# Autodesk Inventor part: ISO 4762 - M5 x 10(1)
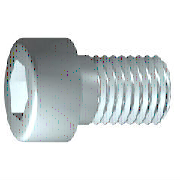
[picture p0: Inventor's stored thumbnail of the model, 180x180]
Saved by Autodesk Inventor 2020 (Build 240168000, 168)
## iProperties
IsCustomPart: 0
Created: 2019-01
Part Number: ISO 4762 - M5 x 10(1)
Material: Nerezová ocel 440C
Description: Šroub s válcovou hlavou s vnitřním šestihranem
Document SubType Name: Modeling
Standard: ISO 4762
Designer: doma
Standard Revision: Fourth edition 2004-03-01
Standards Organization: ISO
Language: cs-CZ
Size Designation: M5 x 10
Categories: <MemberInstance><Categories><Category DisplayName="Spojovací materiál" InternalName="e4da775c-781d-43d5-af7c-5136215cf5a6" Mnemonic="FSTN"><Category DisplayName
Density: 7.75 g/cm^3
Appearance: Pololeštěná
Mass: 3.37173 g
Surface Area: 4.31157 cm^2
Volume: 0.435062 cm^3
Author: doma
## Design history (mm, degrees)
sketch "Náčrt1"
  geometry: L1 (-1.167, 0)-(10, 0); L2 (10, 0)-(10, 2.5); L3 (10, 2.5)-(2, 2.5); L4 (2, 2.5)-(1.509, 2.5); L5 (1.509, 2.5)-(0, 2.5); L6 (0, 2.5)-(0, 4.25); L7 (0, 4.25)-(-5, 4.25); L8 (-5, 4.25)-(-5, 2.309); L9 (-5, 2.309)-(-2.5, 2.309); L10 (-2.5, 2.309)-(-1.167, 0); L11 (-8, 0)-(13, 0) reference; L12 (0, -0.85)-(0, 5.1) reference; L13 (2, 2.5)-(0, 2.5)
  constraints: 22 end point, 6 parallel, 2 collinear, 2 perpendicular, 1 horizontal, 1 point on line
  dimensions: "d1" = 8 distance from line of L3.end L2 (= GEL); "d2" = 0.49086 distance of L4.end L3.end (computed from GAL); "d3" = 5 distance between parallel lines of L8 L6 (= KOH); "d4" = 2.5 distance of L8.end L9.end (= INTI); "d5" = 60 deg angle of L10 L1; "d6" = 5 diameter of L3 L1 (= GD); "d7" = 5 diameter of L5 L1 (= BDM); "d8" = 4.6188 diameter of L9 L1 (= 1.1547 x SW); "d9" = 8.5 diameter of L7 L1 (= KOD); "d26" = 10 distance between parallel lines of L12 L2 (= NLG)
revolve "Těleso" sketch "Náčrt1" stored, may be unused: angle "d10" = 90 deg
sketch "Náčrt2"
  geometry: L1 (0, -5.95)-(0, 5.95) reference; L2 (-5.95, 0)-(5.95, 0) reference; L3 (2.309, 0)-(1.155, -2); L4 (1.155, -2)-(-1.155, -2); L5 (-1.155, -2)-(-2.309, 0); L6 (-2.309, 0)-(-1.155, 2); L7 (-1.155, 2)-(1.155, 2); L8 (1.155, 2)-(2.309, 0); 2 further points
  constraints: 12 end point, 1 coincident, 1 horizontal alignment, 1 point on line, 12 other
extrude "Drážka" join sketch "Náčrt2" stored distance "d11" = 10; taper "d12" = 0 deg
workplane "Work Plane1"
fillet "Fillet2" dims "d30" = 0.1 (= R)
body "Solid1"
fillet "Zaoblení1" dims "d17" = 0.5 (= RR)
feature "Závit" dims "d13" = 8 (= GEL), "d14" = 0
chamfer "Zkosení1" distance "d15" = 0.49076 (= -0.5 x SPD + 0.5 x GD); stored, may be unused: second distance "d16" = 0.49076 (= GUL), angle "d27" = 45 deg
other parameters: "GD" = 5 [user parameter; used in 2 equation terms], "NLG" = 10 [user parameter; used in 1 equation term], "GEL" = 8 [user parameter; used in 2 equation terms], "KOD" = 8.5 [user parameter; used in 1 equation term], "KOH" = 5 [user parameter; used in 1 equation term], "INTI" = 2.5 [user parameter; used in 1 equation term], "GAL" = 0.49076 (= 0.61345 x PTC) [user parameter; used in 1 equation term], "GUL" = 0.49076 (= 0.61345 x PTC) [user parameter; used in 1 equation term], "BDM" = 5 (= NND) [user parameter; used in 1 equation term], "SW" = 4 [user parameter; used in 2 equation terms], "RR" = 0.5 [user parameter; used in 1 equation term], "SPD" = 4.01848 (= NND - 1.2269 x PTC) [user parameter; used in 1 equation term], "d19" = 0, "d28" = 0, "d29" = 0, "R" = 0.1 [user parameter; used in 1 equation term], "TOA" = 30 deg [user parameter], "GD1" = 4.01848 (= THREADDIA - 1.2269 x PTC) [user parameter], "THREADDIA" = 5 [user parameter; used in 1 equation term], "FAWI" = 45 deg [user parameter], "TPU" = 12.5 (computed from PTC) [user parameter], "PTC" = 0.8 [user parameter; used in 5 equation terms], "NND" = 5 [user parameter; used in 2 equation terms], "E0" = 4.62 (= 1.155 x SW) [user parameter]
